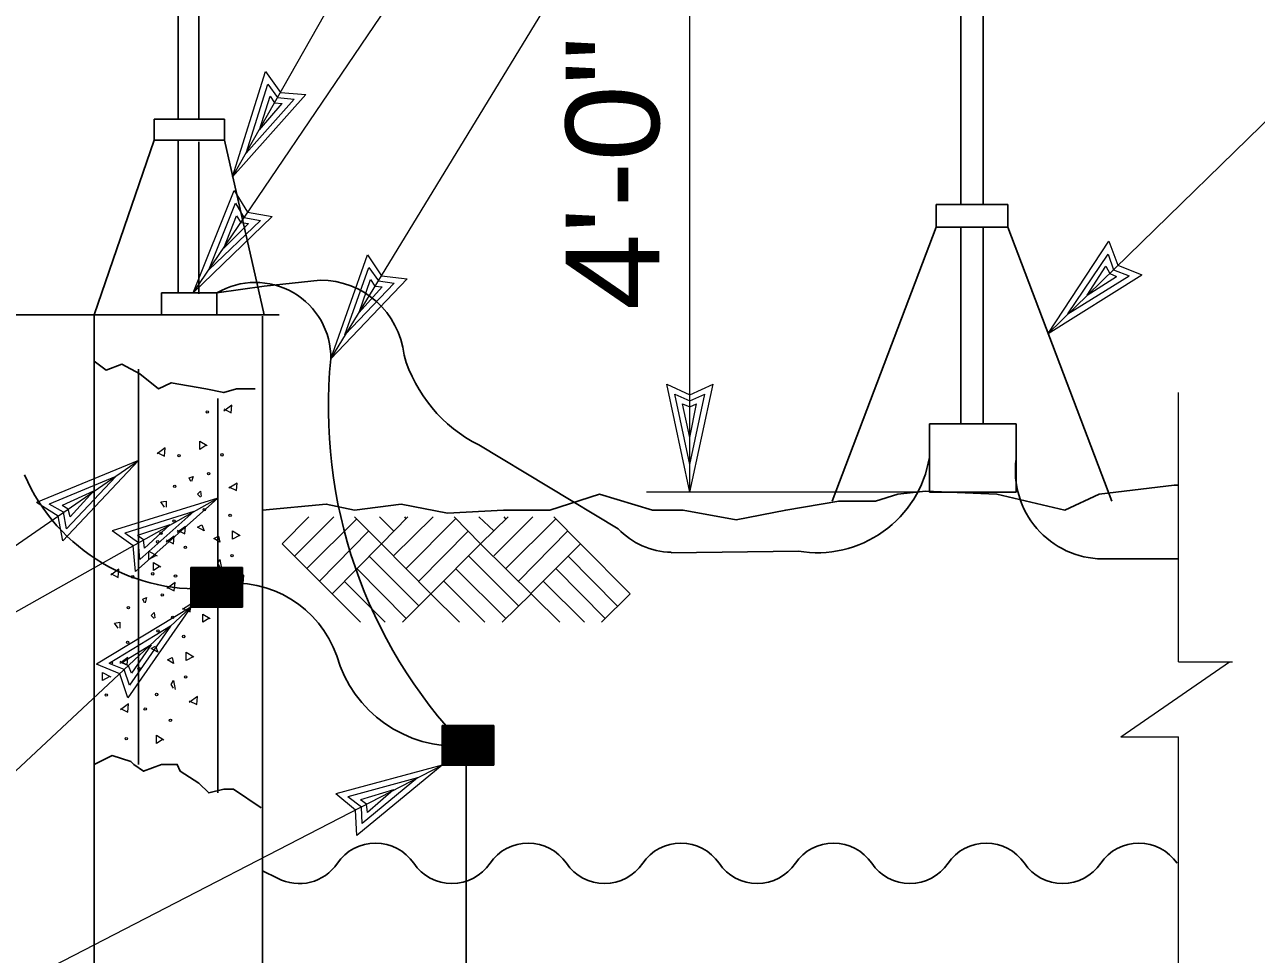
# Model space of a CAD drawing. Extents: x -39.6 to 16.1, y -17.6 to 34.
# Drawn here: x -6.701 to -5.055, y 7.813 to 9.055 of the extents above; entities that cross this region are included whole.
import ezdxf
from ezdxf.enums import TextEntityAlignment as Align

# ---------------------------------------------------------------- set-up
doc = ezdxf.new("R2010")
doc.units = 0
doc.header["$LTSCALE"] = 0.05
doc.layers.add('1', color=7, linetype='Continuous', lineweight=13)
doc.layers.add('2', color=7, linetype='Continuous', lineweight=13)

msp = doc.modelspace()

# ---------------------------------------------------------------- linework, layer by layer
at = {"layer": '1'}
for p, q in [((-6.47621, 8.69642), (-5.52221, 10.10342)), ((-5.81221, 8.43042), (-5.81221, 9.21242)), ((-6.42321, 8.85142), (-6.37921, 8.99242)), ((-6.40521, 8.88342), (-6.37621, 8.97542)), ((-6.37621, 8.97542), (-6.36321, 8.95742)), ((-6.42321, 8.85142), (-6.32521, 8.96142)), ((-6.40521, 8.88342), (-6.34121, 8.95542)), ((-6.38721, 8.91442), (-6.37321, 8.95942)), ((-6.37321, 8.95942), (-6.36721, 8.95042)), ((-6.36321, 8.95742), (-6.34121, 8.95542)), ((-6.38721, 8.91442), (-6.35721, 8.94942)), ((-6.36721, 8.95042), (-6.35721, 8.94942)), ((-6.47621, 8.69642), (-6.42121, 8.83342)), ((-6.45521, 8.72742), (-6.41921, 8.81642)), ((-6.41921, 8.81642), (-6.40821, 8.79742)), ((-6.47621, 8.69642), (-6.37021, 8.79842)), ((-6.45521, 8.72742), (-6.38621, 8.79342)), ((-6.43521, 8.75642), (-6.41821, 8.79942)), ((-6.41821, 8.79942), (-6.41221, 8.79042)), ((-6.41221, 8.79042), (-6.40221, 8.78942)), ((-6.40821, 8.79742), (-6.38621, 8.79342)), ((-6.43521, 8.75642), (-6.40221, 8.78942)), ((-6.29221, 8.60842), (-6.24321, 8.74742)), ((-5.30721, 8.66842), (-5.25321, 8.74842)), ((-5.25321, 8.74842), (-5.24621, 8.72742)), ((-6.27321, 8.64042), (-6.24121, 8.73042)), ((-6.24121, 8.73042), (-6.22821, 8.71242)), ((-5.28121, 8.69342), (-5.25621, 8.73242)), ((-5.25621, 8.73242), (-5.25121, 8.72242)), ((-5.24621, 8.72742), (-5.22521, 8.71942)), ((-6.29221, 8.60842), (-6.19021, 8.71542)), ((-6.27321, 8.64042), (-6.20721, 8.70942)), ((-6.25421, 8.67042), (-6.23921, 8.71442)), ((-6.23921, 8.71442), (-6.23321, 8.70542)), ((-6.22821, 8.71242), (-6.20721, 8.70942)), ((-5.33321, 8.64242), (-5.20821, 8.72042)), ((-5.30721, 8.66842), (-5.22521, 8.71942)), ((-5.28121, 8.69342), (-5.24221, 8.71842)), ((-5.25121, 8.72242), (-5.24221, 8.71842)), ((-6.25421, 8.67042), (-6.22321, 8.70442)), ((-6.23321, 8.70542), (-6.22321, 8.70442)), ((-5.81221, 8.43042), (-5.84321, 8.57442)), ((-5.81221, 8.46742), (-5.83221, 8.56142)), ((-5.83221, 8.56142), (-5.81221, 8.55242)), ((-5.81221, 8.43042), (-5.78121, 8.57442)), ((-5.81221, 8.46742), (-5.79221, 8.56142)), ((-5.81221, 8.55242), (-5.79221, 8.56142)), ((-5.15921, 8.20342), (-5.15921, 8.56342)), ((-5.81221, 8.50342), (-5.82221, 8.54842)), ((-5.82221, 8.54842), (-5.81221, 8.54442)), ((-5.81221, 8.50342), (-5.80321, 8.54842)), ((-5.81221, 8.54442), (-5.80321, 8.54842)), ((-6.54921, 8.47242), (-6.68521, 8.41642)), ((-6.54921, 8.47242), (-6.65021, 8.36542)), ((-6.57921, 8.45142), (-6.66821, 8.41442)), ((-6.57921, 8.45142), (-6.64521, 8.38142)), ((-6.60921, 8.43142), (-6.65121, 8.41242)), ((-6.60921, 8.43142), (-6.64021, 8.39742)), ((-5.51021, 8.43042), (-5.87021, 8.43042)), ((-7.41321, 7.87542), (-6.44321, 8.42242)), ((-6.64921, 8.40342), (-6.66821, 8.41442)), ((-6.64321, 8.40742), (-6.65121, 8.41242)), ((-6.44321, 8.42242), (-6.58421, 8.37842)), ((-6.44321, 8.42242), (-6.55321, 8.32442)), ((-6.64521, 8.38142), (-6.64921, 8.40342)), ((-6.64021, 8.39742), (-6.64321, 8.40742)), ((-6.47521, 8.40442), (-6.56721, 8.37542)), ((-6.47521, 8.40442), (-6.54721, 8.34042)), ((-6.35721, 8.36142), (-6.32121, 8.39742)), ((-6.34021, 8.34542), (-6.28821, 8.39742)), ((-6.22421, 8.36142), (-6.26021, 8.39742)), ((-6.20821, 8.37842), (-6.22721, 8.39742)), ((-6.22421, 8.36142), (-6.18921, 8.39742)), ((-6.22421, 8.36142), (-6.18921, 8.39742)), ((-6.20821, 8.34542), (-6.15521, 8.39742)), ((-6.19121, 8.39442), (-6.19321, 8.39742)), ((-6.09221, 8.36142), (-6.12721, 8.39742)), ((-6.07421, 8.37842), (-6.09421, 8.39742)), ((-6.09221, 8.36142), (-6.05521, 8.39742)), ((-6.07421, 8.34542), (-6.02221, 8.39742)), ((-6.05821, 8.39442), (-6.06021, 8.39742)), ((-5.95821, 8.36142), (-5.99421, 8.39742)), ((-6.50721, 8.38642), (-6.55021, 8.37242)), ((-6.50721, 8.38642), (-6.54121, 8.35542)), ((-6.32421, 8.32842), (-6.25721, 8.39442)), ((-6.30721, 8.31142), (-6.24121, 8.37842)), ((-6.19121, 8.32842), (-6.12521, 8.39442)), ((-6.17421, 8.31142), (-6.10821, 8.37842)), ((-6.05821, 8.32842), (-5.99121, 8.39442)), ((-6.04121, 8.31142), (-5.97521, 8.37842)), ((-6.54921, 8.36242), (-6.56721, 8.37542)), ((-6.54221, 8.36642), (-6.55021, 8.37242)), ((-6.54721, 8.34042), (-6.54921, 8.36242)), ((-6.54121, 8.35542), (-6.54221, 8.36642)), ((-6.29021, 8.29442), (-6.22421, 8.36142)), ((-6.17421, 8.27842), (-6.24121, 8.34542)), ((-6.15821, 8.29442), (-6.22421, 8.36142)), ((-6.15821, 8.29442), (-6.09221, 8.36142)), ((-6.04121, 8.27842), (-6.10821, 8.34542)), ((-6.02521, 8.29442), (-5.95821, 8.36142)), ((-5.90921, 8.27842), (-5.97521, 8.34542)), ((-5.89221, 8.29442), (-5.95821, 8.36142)), ((-6.19121, 8.26142), (-6.25721, 8.32842)), ((-6.05821, 8.26142), (-6.12521, 8.32842)), ((-5.92521, 8.26142), (-5.99121, 8.32842)), ((-6.21921, 8.25642), (-6.27421, 8.31142)), ((-6.08621, 8.25642), (-6.14121, 8.31142)), ((-5.95321, 8.25642), (-6.00821, 8.31142)), ((-6.19621, 8.25642), (-6.15821, 8.29442)), ((-6.12021, 8.25642), (-6.15821, 8.29442)), ((-6.06321, 8.25642), (-6.02421, 8.29442)), ((-5.93021, 8.25642), (-5.89221, 8.29442)), ((-6.47921, 8.27642), (-6.60521, 8.20042)), ((-6.47921, 8.27642), (-6.56321, 8.15542)), ((-6.50621, 8.25142), (-6.58821, 8.20142)), ((-6.50621, 8.25142), (-6.56121, 8.17242)), ((-6.53221, 8.22642), (-6.57121, 8.20242)), ((-6.53221, 8.22642), (-6.55821, 8.18842)), ((-6.56821, 8.19342), (-6.58821, 8.20142)), ((-6.56221, 8.19842), (-6.57121, 8.20242)), ((-6.55821, 8.18842), (-6.56221, 8.19842)), ((-5.23621, 8.10342), (-5.09121, 8.20342)), ((-5.15921, 8.20342), (-5.08721, 8.20342)), ((-6.56121, 8.17242), (-6.56821, 8.19342)), ((-5.23621, 8.10342), (-5.15921, 8.10342)), ((-5.15921, 7.52342), (-5.15921, 8.10342)), ((-7.39621, 7.41942), (-6.14321, 8.06542)), ((-6.14321, 8.06542), (-6.28521, 8.02742)), ((-6.14321, 8.06542), (-6.25721, 7.97142)), ((-6.17621, 8.04842), (-6.26921, 8.02342)), ((-6.17621, 8.04842), (-6.25021, 7.98742)), ((-6.25121, 8.00942), (-6.26921, 8.02342)), ((-6.20821, 8.03242), (-6.25221, 8.01942)), ((-6.24421, 8.01342), (-6.25221, 8.01942)), ((-6.20821, 8.03242), (-6.24321, 8.00242)), ((-6.25021, 7.98742), (-6.25121, 8.00942)), ((-6.24321, 8.00242), (-6.24421, 8.01342))]:
    msp.add_line(p, q, dxfattribs=at)
at = {"layer": '1', "lineweight": 25}
for p, q in [((-6.49621, 8.92842), (-6.49621, 9.27042)), ((-6.46821, 8.92842), (-6.46821, 9.27042)), ((-5.45021, 8.81442), (-5.45021, 9.14242)), ((-5.42021, 8.81442), (-5.42021, 9.14242)), ((-6.52821, 8.92842), (-6.43421, 8.92842)), ((-6.52821, 8.90042), (-6.52821, 8.92842)), ((-6.43421, 8.90042), (-6.43421, 8.92842)), ((-6.52821, 8.90042), (-6.60821, 8.66742)), ((-6.52821, 8.90042), (-6.43421, 8.90042)), ((-6.49621, 8.69642), (-6.49621, 8.89942)), ((-6.46821, 8.69542), (-6.46821, 8.89842)), ((-6.43421, 8.90042), (-6.38121, 8.66742)), ((-5.48321, 8.81442), (-5.38721, 8.81442)), ((-5.48321, 8.78442), (-5.48321, 8.81442)), ((-5.48321, 8.78442), (-5.62221, 8.41842)), ((-5.45021, 8.52142), (-5.45021, 8.78442)), ((-5.42021, 8.52142), (-5.42021, 8.78342)), ((-5.38721, 8.78442), (-5.24821, 8.41842)), ((-6.51821, 8.69642), (-6.44421, 8.69642)), ((-6.51821, 8.69642), (-6.51821, 8.66642)), ((-6.44421, 8.69642), (-6.44421, 8.66742)), ((-7.01121, 8.66742), (-6.36121, 8.66742)), ((-6.60821, 7.20842), (-6.60821, 8.66642)), ((-6.54921, 8.06642), (-6.54921, 8.59442)), ((-6.44321, 8.02842), (-6.44321, 8.55542)), ((-5.49221, 8.52142), (-5.37621, 8.52142)), ((-6.09421, 8.49342), (-5.90821, 8.38142)), ((-5.49221, 8.43042), (-5.37621, 8.43042)), ((-5.83721, 8.34942), (-5.66721, 8.35142)), ((-6.47921, 8.27642), (-6.47921, 8.32942)), ((-6.47921, 8.32942), (-6.41021, 8.32942)), ((-6.41021, 8.27642), (-6.41021, 8.32942)), ((-5.26121, 8.34142), (-5.15921, 8.34142)), ((-6.47921, 8.32842), (-6.41021, 8.32842)), ((-6.47921, 8.32742), (-6.41021, 8.32742)), ((-6.47921, 8.32642), (-6.41021, 8.32642)), ((-6.47921, 8.32542), (-6.41021, 8.32542)), ((-6.47921, 8.32442), (-6.41021, 8.32442)), ((-6.47921, 8.32342), (-6.41021, 8.32342)), ((-6.47921, 8.32242), (-6.41021, 8.32242)), ((-6.47921, 8.32142), (-6.41021, 8.32142)), ((-6.47921, 8.32042), (-6.41021, 8.32042)), ((-6.47921, 8.31942), (-6.41021, 8.31942)), ((-6.47921, 8.31842), (-6.41021, 8.31842)), ((-6.47921, 8.31742), (-6.41021, 8.31742)), ((-6.47921, 8.31642), (-6.41021, 8.31642)), ((-6.47921, 8.31542), (-6.41021, 8.31542)), ((-6.47921, 8.31442), (-6.41021, 8.31442)), ((-6.47921, 8.31342), (-6.41021, 8.31342)), ((-6.47921, 8.31242), (-6.41021, 8.31242)), ((-6.47921, 8.31142), (-6.41021, 8.31142)), ((-6.47921, 8.31042), (-6.41021, 8.31042)), ((-6.47921, 8.30942), (-6.41021, 8.30942)), ((-6.47921, 8.30842), (-6.41021, 8.30842)), ((-6.47921, 8.30742), (-6.41021, 8.30742)), ((-6.47921, 8.30642), (-6.41021, 8.30642)), ((-6.47921, 8.30542), (-6.41021, 8.30542)), ((-6.47921, 8.30442), (-6.41021, 8.30442)), ((-6.47921, 8.30342), (-6.41021, 8.30342)), ((-6.47921, 8.30242), (-6.41021, 8.30242)), ((-6.47921, 8.30142), (-6.41021, 8.30142)), ((-6.47921, 8.30042), (-6.41021, 8.30042)), ((-6.47921, 8.29942), (-6.41021, 8.29942)), ((-6.47921, 8.29842), (-6.41021, 8.29842)), ((-6.47921, 8.29742), (-6.41021, 8.29742)), ((-6.47921, 8.29642), (-6.41021, 8.29642)), ((-6.47921, 8.29542), (-6.41021, 8.29542)), ((-6.47921, 8.29442), (-6.41021, 8.29442)), ((-6.47921, 8.29342), (-6.41021, 8.29342)), ((-6.47921, 8.29242), (-6.41021, 8.29242)), ((-6.47921, 8.29142), (-6.41021, 8.29142)), ((-6.47921, 8.29042), (-6.41021, 8.29042)), ((-6.47921, 8.28942), (-6.41021, 8.28942)), ((-6.47921, 8.28842), (-6.41021, 8.28842)), ((-6.47921, 8.28742), (-6.41021, 8.28742)), ((-6.47921, 8.28642), (-6.41021, 8.28642)), ((-6.47921, 8.28542), (-6.41021, 8.28542)), ((-6.47921, 8.28442), (-6.41021, 8.28442)), ((-6.47921, 8.28342), (-6.41021, 8.28342)), ((-6.47921, 8.28242), (-6.41021, 8.28242)), ((-6.47921, 8.28142), (-6.41021, 8.28142)), ((-6.47921, 8.28042), (-6.41021, 8.28042)), ((-6.47921, 8.27942), (-6.41021, 8.27942)), ((-6.47921, 8.27842), (-6.41021, 8.27842)), ((-6.47921, 8.27742), (-6.41021, 8.27742)), ((-6.47921, 8.27642), (-6.41021, 8.27642)), ((-6.14321, 8.06542), (-6.14321, 8.11842)), ((-6.14321, 8.11842), (-6.07421, 8.11842)), ((-6.14321, 8.11742), (-6.07421, 8.11742)), ((-6.14321, 8.11642), (-6.07421, 8.11642)), ((-6.14321, 8.11542), (-6.07421, 8.11542)), ((-6.07421, 8.06542), (-6.07421, 8.11842)), ((-6.14321, 8.11442), (-6.07421, 8.11442)), ((-6.14321, 8.11342), (-6.07421, 8.11342)), ((-6.14321, 8.11242), (-6.07421, 8.11242)), ((-6.14321, 8.11142), (-6.07421, 8.11142)), ((-6.14321, 8.11042), (-6.07421, 8.11042)), ((-6.14321, 8.10942), (-6.07421, 8.10942)), ((-6.14321, 8.10842), (-6.07421, 8.10842)), ((-6.14321, 8.10742), (-6.07421, 8.10742)), ((-6.14321, 8.10642), (-6.07421, 8.10642)), ((-6.14321, 8.10542), (-6.07421, 8.10542)), ((-6.14321, 8.10442), (-6.07421, 8.10442)), ((-6.14321, 8.10342), (-6.07421, 8.10342)), ((-6.14321, 8.10242), (-6.07421, 8.10242)), ((-6.14321, 8.10142), (-6.07421, 8.10142)), ((-6.14321, 8.10042), (-6.07421, 8.10042)), ((-6.14321, 8.09942), (-6.07421, 8.09942)), ((-6.14321, 8.09842), (-6.07421, 8.09842)), ((-6.14321, 8.09742), (-6.07421, 8.09742)), ((-6.14321, 8.09642), (-6.07421, 8.09642)), ((-6.14321, 8.09542), (-6.07421, 8.09542)), ((-6.14321, 8.09442), (-6.07421, 8.09442)), ((-6.14321, 8.09342), (-6.07421, 8.09342)), ((-6.14321, 8.09242), (-6.07421, 8.09242)), ((-6.14321, 8.09142), (-6.07421, 8.09142)), ((-6.14321, 8.09042), (-6.07421, 8.09042)), ((-6.14321, 8.08942), (-6.07421, 8.08942)), ((-6.14321, 8.08842), (-6.07421, 8.08842)), ((-6.14321, 8.08742), (-6.07421, 8.08742)), ((-6.14321, 8.08642), (-6.07421, 8.08642)), ((-6.14321, 8.08542), (-6.07421, 8.08542)), ((-6.14321, 8.08442), (-6.07421, 8.08442)), ((-6.14321, 8.08342), (-6.07421, 8.08342)), ((-6.14321, 8.08242), (-6.07421, 8.08242)), ((-6.11121, 8.09542), (-6.11121, 7.20742)), ((-6.14321, 8.08142), (-6.07421, 8.08142)), ((-6.14321, 8.08042), (-6.07421, 8.08042)), ((-6.14321, 8.07942), (-6.07421, 8.07942)), ((-6.14321, 8.07842), (-6.07421, 8.07842)), ((-6.14321, 8.07742), (-6.07421, 8.07742)), ((-6.14321, 8.07642), (-6.07421, 8.07642)), ((-6.14321, 8.07542), (-6.07421, 8.07542)), ((-6.14321, 8.07442), (-6.07421, 8.07442)), ((-6.14321, 8.07342), (-6.07421, 8.07342)), ((-6.14321, 8.07242), (-6.07421, 8.07242)), ((-6.14321, 8.07142), (-6.07421, 8.07142)), ((-6.14321, 8.07042), (-6.07421, 8.07042)), ((-6.14321, 8.06942), (-6.07421, 8.06942)), ((-6.14321, 8.06842), (-6.07421, 8.06842)), ((-6.14321, 8.06742), (-6.07421, 8.06742)), ((-6.14321, 8.06642), (-6.07421, 8.06642)), ((-6.14321, 8.06542), (-6.07421, 8.06542)), ((-6.36321, 7.91442), (-6.38321, 7.92442))]:
    msp.add_line(p, q, dxfattribs=at)
at = {"layer": '1'}
for points in [[(-6.42321, 8.85142), (-5.91121, 9.75442), (-6.04621, 9.75442)], [(-6.29221, 8.60842), (-5.82021, 9.38142), (-5.69621, 9.38142)], [(-4.92421, 9.04142), (-5.33321, 8.64242), (-5.25221, 8.76542)], [(-6.37921, 8.99242), (-6.35921, 8.96442), (-6.32521, 8.96142)], [(-6.42121, 8.83342), (-6.40321, 8.80442), (-6.37021, 8.79842)], [(-5.25221, 8.76542), (-5.24021, 8.73342), (-5.20821, 8.72042)], [(-6.24321, 8.74742), (-6.22421, 8.71942), (-6.19021, 8.71542)], [(-5.84321, 8.57442), (-5.81221, 8.56042), (-5.78121, 8.57442)], [(-7.62021, 7.87542), (-7.41321, 7.87542), (-6.54921, 8.47242)], [(-6.65021, 8.36542), (-6.65621, 8.39842), (-6.68521, 8.41642)], [(-5.98621, 8.25642), (-6.09221, 8.36142), (-6.05521, 8.39742)], [(-6.55321, 8.32442), (-6.55621, 8.35842), (-6.58421, 8.37842)], [(-6.25221, 8.25642), (-6.29021, 8.29442), (-6.35721, 8.36142)], [(-7.69521, 7.41942), (-7.39621, 7.41942), (-6.47921, 8.27642)], [(-6.56321, 8.15542), (-6.57421, 8.18742), (-6.60521, 8.20042)], [(-6.25721, 7.97142), (-6.25921, 8.00542), (-6.28521, 8.02742)]]:
    msp.add_lwpolyline(points, dxfattribs=at)
at = {"layer": '1', "lineweight": 25}
for points in [[(-5.48321, 8.78442), (-5.38721, 8.78442), (-5.38721, 8.81442)], [(-6.44421, 8.69642), (-6.38121, 8.70542), (-6.30621, 8.71342)], [(-6.38321, 7.20842), (-6.38321, 8.30642), (-6.38321, 8.47642), (-6.38321, 8.66542)], [(-6.60821, 8.60542), (-6.59221, 8.59342), (-6.57121, 8.60142), (-6.54721, 8.58842), (-6.52221, 8.56842), (-6.50521, 8.57642), (-6.45921, 8.56842), (-6.43521, 8.56342), (-6.41821, 8.56842), (-6.39321, 8.56842)], [(-5.49221, 8.43042), (-5.49221, 8.47642), (-5.49221, 8.52142)], [(-5.37621, 8.43042), (-5.37621, 8.47642), (-5.37621, 8.52142)], [(-6.38321, 8.40642), (-6.29821, 8.41442), (-6.26021, 8.40642), (-6.19821, 8.41442), (-6.13621, 8.40242), (-6.06121, 8.40642), (-5.99921, 8.40642), (-5.93321, 8.42742), (-5.86221, 8.40642), (-5.82121, 8.40642), (-5.75021, 8.39342), (-5.68421, 8.40642), (-5.61321, 8.41842), (-5.56421, 8.41842), (-5.53421, 8.42742), (-5.49721, 8.43142), (-5.40221, 8.42742), (-5.31121, 8.40642), (-5.26521, 8.42742), (-5.16521, 8.43942), (-5.15921, 8.43942)], [(-6.60821, 8.06642), (-6.58421, 8.07842), (-6.55921, 8.07042), (-6.55521, 8.06642), (-6.54221, 8.05742), (-6.51821, 8.06642), (-6.49721, 8.06642), (-6.49321, 8.05742), (-6.46821, 8.04142), (-6.45521, 8.02842), (-6.43521, 8.03342), (-6.42221, 8.03342), (-6.38521, 8.00842)]]:
    msp.add_lwpolyline(points, dxfattribs=at)
for centre, radius, start, end in [((-6.39282, 8.60962), 0.10087, 359.30638, 120.62858), ((-6.30586, 8.60109), 0.11233, 6.30147, 90.17793), ((-6.00754, 8.6673), 0.19429, 196.10252, 243.50862), ((-5.63934, 8.54405), 0.65603, 174.36966, 223.6269), ((-5.64211, 8.50128), 0.15195, 260.49156, 350.5838), ((-5.25969, 8.45869), 0.11758, 172.31111, 269.26427), ((-6.47004, 8.55248), 0.2515, 203.19644, 276.12514), ((-5.83447, 8.45212), 0.10216, 223.79579, 268.42691), ((-6.42118, 8.16379), 0.14502, 19.17326, 97.93809), ((-6.1244, 8.2573), 0.16626, 196.01973, 273.86141), ((-6.23221, 7.89992), 0.06157, 34.0772, 145.92281), ((-6.02821, 7.89992), 0.06157, 34.0772, 145.92281), ((-5.82421, 7.89992), 0.06157, 34.0772, 145.92281), ((-5.62021, 7.89992), 0.06157, 34.0772, 145.92281), ((-5.41621, 7.89992), 0.06157, 34.0772, 145.92281), ((-5.21221, 7.89992), 0.06157, 34.0772, 145.92281), ((-6.33421, 7.96892), 0.06157, 242.03288, 325.92281), ((-6.13021, 7.96892), 0.06157, 214.0772, 325.92281), ((-5.92621, 7.96892), 0.06157, 214.0772, 325.92281), ((-5.72221, 7.96892), 0.06157, 214.0772, 325.92281), ((-5.51821, 7.96892), 0.06157, 214.0772, 325.92281), ((-5.31421, 7.96892), 0.06157, 214.0772, 325.92281)]:
    msp.add_arc(centre, radius, start, end, dxfattribs=at)
at = {"layer": '2'}
for p, q in [((-6.51421, 8.41042), (-6.51921, 8.41742)), ((-6.57621, 8.24842), (-6.58121, 8.25542))]:
    msp.add_line(p, q, dxfattribs=at)
for points in [[(-6.43521, 8.54142), (-6.42521, 8.53642), (-6.42421, 8.54642), (-6.43521, 8.53842)], [(-6.45921, 8.49242), (-6.46721, 8.48742), (-6.46721, 8.49842), (-6.45721, 8.49242)], [(-6.52421, 8.48342), (-6.51421, 8.47842), (-6.51321, 8.48942), (-6.52421, 8.48142)], [(-6.47921, 8.44442), (-6.48121, 8.44942), (-6.47621, 8.45142), (-6.47821, 8.44442)], [(-6.46621, 8.42342), (-6.47021, 8.42742), (-6.46621, 8.43142), (-6.46521, 8.42442)], [(-6.42821, 8.43742), (-6.41821, 8.43242), (-6.41721, 8.44242), (-6.42821, 8.43542)], [(-6.51921, 8.41742), (-6.51221, 8.41842), (-6.51221, 8.41042)], [(-6.49721, 8.37942), (-6.48721, 8.37442), (-6.48621, 8.38442), (-6.49721, 8.37642)], [(-6.41421, 8.37242), (-6.42321, 8.36742), (-6.42321, 8.37842), (-6.41321, 8.37242)], [(-6.51221, 8.36642), (-6.50221, 8.36142), (-6.50121, 8.37142), (-6.51221, 8.36342)], [(-6.52621, 8.34542), (-6.53521, 8.34042), (-6.53521, 8.35142), (-6.52421, 8.34542)], [(-6.52121, 8.33042), (-6.52921, 8.32542), (-6.52921, 8.33642), (-6.51921, 8.33042)], [(-6.44021, 8.33042), (-6.44321, 8.33542), (-6.44021, 8.34042), (-6.43821, 8.32842)], [(-6.58621, 8.32142), (-6.57621, 8.31642), (-6.57521, 8.32742), (-6.58621, 8.31942)], [(-6.41921, 8.31342), (-6.40921, 8.30842), (-6.40821, 8.31942), (-6.41921, 8.31142)], [(-6.51121, 8.30342), (-6.50121, 8.29842), (-6.50021, 8.30942), (-6.51121, 8.30142)], [(-6.54121, 8.28242), (-6.54321, 8.28742), (-6.53821, 8.28942), (-6.54021, 8.28242)], [(-6.49021, 8.27542), (-6.48021, 8.27042), (-6.47921, 8.28042), (-6.49021, 8.27342)], [(-6.52821, 8.26142), (-6.53221, 8.26542), (-6.52821, 8.26942), (-6.52721, 8.26242)], [(-6.45521, 8.26142), (-6.46321, 8.25642), (-6.46321, 8.26742), (-6.45321, 8.26142)], [(-6.58121, 8.25542), (-6.57421, 8.25642), (-6.57421, 8.24842)], [(-6.47621, 8.21042), (-6.48521, 8.20542), (-6.48521, 8.21642), (-6.47521, 8.21042)], [(-6.57421, 8.20442), (-6.56421, 8.19942), (-6.56321, 8.20942), (-6.57421, 8.20142)], [(-6.58821, 8.18342), (-6.59721, 8.17842), (-6.59721, 8.18942), (-6.58621, 8.18342)], [(-6.50221, 8.16842), (-6.50521, 8.17342), (-6.50221, 8.17842), (-6.50021, 8.16642)], [(-6.48121, 8.15142), (-6.47121, 8.14642), (-6.47021, 8.15742), (-6.48121, 8.14942)], [(-6.57321, 8.14142), (-6.56321, 8.13642), (-6.56221, 8.14742), (-6.57321, 8.13942)], [(-6.51721, 8.09942), (-6.52521, 8.09442), (-6.52521, 8.10542), (-6.51521, 8.09942)]]:
    msp.add_lwpolyline(points, dxfattribs=at)
for points in [[(-6.46121, 8.37842), (-6.47021, 8.38342), (-6.46421, 8.38642)], [(-6.44021, 8.36342), (-6.44821, 8.36842), (-6.44221, 8.37142)], [(-6.52321, 8.21642), (-6.53221, 8.22142), (-6.52621, 8.22442)], [(-6.50221, 8.20142), (-6.51021, 8.20642), (-6.50421, 8.20942)]]:
    msp.add_lwpolyline(points, close=True, dxfattribs=at)
for centre in [(-6.45708, 8.53742), (-6.49483, 8.47917), (-6.43758, 8.48017), (-6.45533, 8.45492), (-6.50058, 8.43792), (-6.46108, 8.40692), (-6.42658, 8.39942), (-6.50158, 8.39167), (-6.52333, 8.36392), (-6.51908, 8.37542), (-6.48633, 8.35642), (-6.42408, 8.34542), (-6.55683, 8.31717), (-6.53008, 8.32117), (-6.49958, 8.31817), (-6.46283, 8.32192), (-6.47808, 8.30267), (-6.51733, 8.29292), (-6.44433, 8.28742), (-6.56258, 8.27592), (-6.50333, 8.26292), (-6.52308, 8.24492), (-6.56358, 8.22967), (-6.48858, 8.23742), (-6.58533, 8.20192), (-6.54833, 8.19442), (-6.48608, 8.18342), (-6.59208, 8.15917), (-6.52483, 8.15992), (-6.54008, 8.14067), (-6.50633, 8.12542), (-6.56533, 8.10092)]:
    msp.add_circle(centre, 0.00162, dxfattribs=at)

# ---------------------------------------------------------------- texts
at = {"layer": '1', "width": 1.1}
msp.add_text('4\'-0"', height=0.125, rotation=90, dxfattribs=at).set_placement((-5.85321, 8.85642), align=Align.CENTER)

doc.saveas('drawing.dxf')
